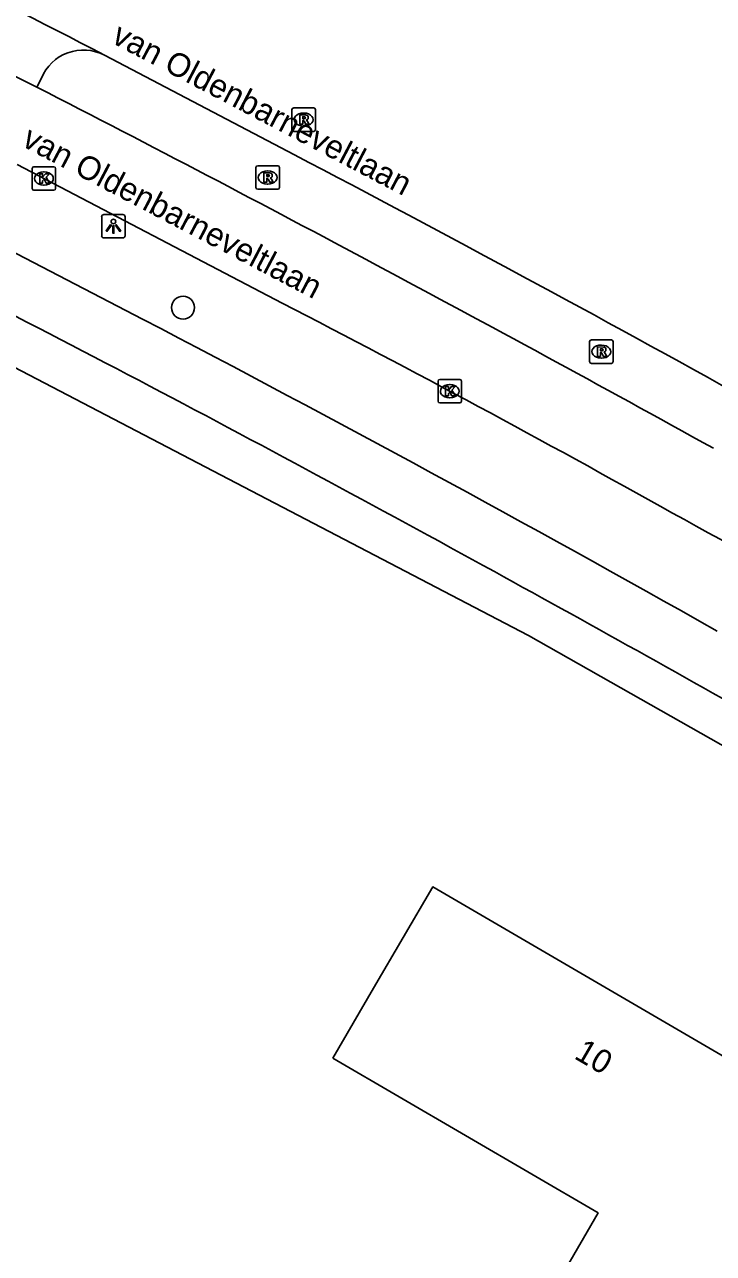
# Model space of a CAD drawing. Extents: x 162417 to 163721, y 384268 to 385416.
# Drawn here: x 163258.8 to 163288.2, y 385291.7 to 385344.1 of the extents above; entities that cross this region are included whole.
import ezdxf

# ---------------------------------------------------------------- set-up
doc = ezdxf.new("R2010")
doc.units = 0
for name, color, linetype in [('IMGEO_Boom', 7, 'Continuous'), ('IMGEO_Fietspad_open', 7, 'Continuous'), ('IMGEO_Kolk', 7, 'Continuous'), ('IMGEO_Lichtpunt', 7, 'Continuous'), ('IMGEO_Openbare_ruimte_label', 7, 'Continuous'), ('IMGEO_Pand', 7, 'Continuous'), ('IMGEO_Pand_nummerreeks', 7, 'Continuous'), ('IMGEO_Rijbaan_lokaal_gesloten', 7, 'Continuous'), ('IMGEO_Rijbaan_lokaal_open', 7, 'Continuous'), ('IMGEO_Rioolput', 7, 'Continuous'), ('IMGEO_Voetpad_open', 7, 'Continuous')]:
    doc.layers.add(name, color=color, linetype=linetype)

msp = doc.modelspace()

# ---------------------------------------------------------------- linework, layer by layer
at = {"layer": 'IMGEO_Boom'}
msp.add_circle((163265.554, 385332.056), 0.489, dxfattribs=at)
at = {"layer": 'IMGEO_Fietspad_open'}
msp.add_lwpolyline([(163254.163, 385336.585), (163263.832, 385331.566)], dxfattribs=at)
for centre, radius, start, end in [((162861.635, 384564.02), 864.147, 61.133149, 63.416417), ((162868.056, 384573.863), 854.84, 60.5517, 62.420278), ((162780.171, 384413.91), 1034.935, 59.552708, 61.195582)]:
    msp.add_arc(centre, radius, start, end, dxfattribs=at)
at = {"layer": 'IMGEO_Kolk'}
for p, q in [((163259.122, 385337.139), (163259.122, 385337.991)), ((163259.197, 385338.065), (163260.049, 385338.065)), ((163260.123, 385337.991), (163260.123, 385337.139)), ((163259.61, 385337.845), (163259.635, 385337.845)), ((163260.049, 385337.065), (163259.197, 385337.065)), ((163259.633, 385337.285), (163259.608, 385337.285)), ((163276.423, 385328.064), (163276.423, 385328.916)), ((163276.498, 385328.99), (163277.35, 385328.99)), ((163276.911, 385328.77), (163276.936, 385328.77)), ((163277.424, 385328.916), (163277.424, 385328.064)), ((163277.35, 385327.99), (163276.498, 385327.99)), ((163276.934, 385328.21), (163276.909, 385328.21))]:
    msp.add_line(p, q, dxfattribs=at)
for points in [[(163259.122, 385337.139), (163259.122, 385337.991)], [(163259.197, 385338.065), (163260.049, 385338.065)], [(163260.123, 385337.991), (163260.123, 385337.139)], [(163259.443, 385337.765), (163259.566, 385337.765), (163259.566, 385337.614), (163259.696, 385337.765), (163259.86, 385337.765), (163259.714, 385337.614), (163259.867, 385337.365), (163259.715, 385337.365), (163259.63, 385337.529), (163259.566, 385337.462), (163259.566, 385337.365), (163259.443, 385337.365), (163259.443, 385337.765)], [(163260.049, 385337.065), (163259.197, 385337.065)], [(163276.423, 385328.064), (163276.423, 385328.916)], [(163276.498, 385328.99), (163277.35, 385328.99)], [(163276.744, 385328.69), (163276.867, 385328.69), (163276.867, 385328.539), (163276.997, 385328.69), (163277.161, 385328.69), (163277.015, 385328.539), (163277.168, 385328.29), (163277.016, 385328.29), (163276.931, 385328.454), (163276.867, 385328.387), (163276.867, 385328.29), (163276.744, 385328.29), (163276.744, 385328.69)], [(163277.424, 385328.916), (163277.424, 385328.064)], [(163277.35, 385327.99), (163276.498, 385327.99)]]:
    msp.add_lwpolyline(points, dxfattribs=at)
for centre, start, end in [((163259.199, 385337.989), 91.552, 178.448), ((163259.199, 385337.989), 91.552, 178.448), ((163260.047, 385337.989), 1.552, 88.448), ((163260.047, 385337.989), 1.552, 88.448), ((163259.199, 385337.141), 181.552, 268.448), ((163259.199, 385337.141), 181.552, 268.448), ((163260.047, 385337.141), 271.552, 358.448), ((163260.047, 385337.141), 271.552, 358.448), ((163276.5, 385328.914), 91.552, 178.448), ((163276.5, 385328.914), 91.552, 178.448), ((163277.348, 385328.914), 1.552, 88.448), ((163277.348, 385328.914), 1.552, 88.448), ((163276.5, 385328.066), 181.552, 268.448), ((163276.5, 385328.066), 181.552, 268.448), ((163277.348, 385328.066), 271.552, 358.448), ((163277.348, 385328.066), 271.552, 358.448)]:
    msp.add_arc(centre, 0.0765, start, end, dxfattribs=at)
for centre, major_axis, ratio, start_param, end_param in [((163259.609, 385337.565), (-0.387, 0.002), 0.722429, 4.712389, 7.853982), ((163259.634, 385337.565), (-0.39, 0.002), 0.717154, 1.570796, 4.712389), ((163276.91, 385328.49), (-0.387, 0.002), 0.722429, 4.712389, 7.853982), ((163276.935, 385328.49), (-0.39, 0.002), 0.717154, 1.570796, 4.712389)]:
    msp.add_ellipse(centre, major_axis=major_axis, ratio=ratio, start_param=start_param, end_param=end_param, dxfattribs=at)
at = {"layer": 'IMGEO_Lichtpunt'}
for p, q in [((163262.085, 385335.931), (163262.085, 385335.124)), ((163262.085, 385335.931), (163262.085, 385335.124)), ((163262.987, 385336.026), (163262.179, 385336.026)), ((163262.987, 385336.026), (163262.179, 385336.026)), ((163263.081, 385335.124), (163263.081, 385335.931)), ((163263.081, 385335.124), (163263.081, 385335.931)), ((163262.179, 385335.03), (163262.987, 385335.03)), ((163262.179, 385335.03), (163262.987, 385335.03))]:
    msp.add_line(p, q, dxfattribs=at)
for points in [[(163262.459, 385335.595), (163262.498, 385335.567), (163262.31, 385335.305), (163262.272, 385335.332), (163262.459, 385335.595)], [(163262.561, 385335.547), (163262.608, 385335.547), (163262.608, 385335.225), (163262.561, 385335.225), (163262.561, 385335.547)], [(163262.671, 385335.567), (163262.709, 385335.594), (163262.896, 385335.332), (163262.857, 385335.304), (163262.671, 385335.567)]]:
    msp.add_lwpolyline(points, dxfattribs=at)
msp.add_circle((163262.584, 385335.729), 0.0994, dxfattribs=at)
for centre, start, end in [((163262.179, 385335.931), 90, 180), ((163262.179, 385335.931), 90, 180), ((163262.987, 385335.931), 0, 90), ((163262.987, 385335.931), 0, 90), ((163262.179, 385335.124), 180, 270), ((163262.179, 385335.124), 180, 270), ((163262.987, 385335.124), 270, 0), ((163262.987, 385335.124), 270, 360)]:
    msp.add_arc(centre, 0.0946, start, end, dxfattribs=at)
at = {"layer": 'IMGEO_Pand'}
msp.add_lwpolyline([(163271.934, 385300.031), (163273.678, 385303.02), (163276.197, 385307.338), (163292.739, 385297.685), (163292.512, 385297.296), (163288.42, 385290.282), (163292.911, 385287.661), (163284.217, 385272.761), (163279.899, 385275.28), (163276.875, 385277.044), (163277, 385277.259), (163277.431, 385277.007), (163284.546, 385289.202), (163281.738, 385290.839), (163283.249, 385293.43), (163271.934, 385300.031)], dxfattribs=at)
at = {"layer": 'IMGEO_Rijbaan_lokaal_gesloten'}
for points in [[(163259.326, 385341.462), (163256.813, 385342.718), (163246.464, 385347.868)], [(163262.2, 385342.827), (163270.31, 385338.574)], [(163258.488, 385338.155), (163269.784, 385332.244)]]:
    msp.add_lwpolyline(points, dxfattribs=at)
for centre, radius, start, end in [((163041.904, 384919.915), 476.849, 62.48489, 64.68209), ((162780.756, 384411.16), 1046.18, 60.986906, 62.777614), ((162832.495, 384505.225), 941.357, 60.941053, 62.284021), ((163022.094, 384852.214), 540.166, 60.70323, 62.70676), ((163050.012, 384890.752), 492.926, 59.1843, 61.34126)]:
    msp.add_arc(centre, radius, start, end, dxfattribs=at)
at = {"layer": 'IMGEO_Rijbaan_lokaal_open'}
msp.add_lwpolyline([(163259.513, 385341.847), (163259.326, 385341.462)], dxfattribs=at)
msp.add_arc((163261.307, 385341.103), 1.942, 62.6131, 157.4626, dxfattribs=at)
at = {"layer": 'IMGEO_Rioolput'}
for p, q in [((163270.273, 385340.576), (163271.125, 385340.576)), ((163270.198, 385339.65), (163270.198, 385340.502)), ((163270.686, 385340.356), (163270.711, 385340.356)), ((163271.199, 385340.502), (163271.199, 385339.65)), ((163271.125, 385339.576), (163270.273, 385339.576)), ((163270.709, 385339.796), (163270.684, 385339.796)), ((163268.661, 385337.18), (163268.661, 385338.032)), ((163268.736, 385338.106), (163269.588, 385338.106)), ((163269.662, 385338.032), (163269.662, 385337.18)), ((163269.149, 385337.886), (163269.174, 385337.886)), ((163269.588, 385337.106), (163268.736, 385337.106)), ((163269.172, 385337.326), (163269.147, 385337.326)), ((163282.886, 385329.751), (163282.886, 385330.603)), ((163282.961, 385330.677), (163283.813, 385330.677)), ((163283.887, 385330.603), (163283.887, 385329.751)), ((163283.374, 385330.457), (163283.399, 385330.457)), ((163283.813, 385329.677), (163282.961, 385329.677)), ((163283.397, 385329.897), (163283.372, 385329.897))]:
    msp.add_line(p, q, dxfattribs=at)
for points in [[(163270.273, 385340.576), (163271.125, 385340.576)], [(163270.198, 385339.65), (163270.198, 385340.502)], [(163270.787, 385340.274), (163270.535, 385340.276), (163270.535, 385339.876)], [(163270.535, 385339.876), (163270.659, 385339.876), (163270.659, 385340.038), (163270.67, 385340.038)], [(163270.713, 385340.195), (163270.659, 385340.195), (163270.659, 385340.114)], [(163270.659, 385340.114), (163270.711, 385340.114)], [(163271.199, 385340.502), (163271.199, 385339.65)], [(163271.125, 385339.576), (163270.273, 385339.576)], [(163270.717, 385340.009), (163270.788, 385339.876), (163270.928, 385339.876), (163270.863, 385340.002)], [(163268.661, 385337.18), (163268.661, 385338.032)], [(163268.736, 385338.106), (163269.588, 385338.106)], [(163269.662, 385338.032), (163269.662, 385337.18)], [(163269.25, 385337.804), (163268.998, 385337.806), (163268.998, 385337.406)], [(163268.998, 385337.406), (163269.122, 385337.406), (163269.122, 385337.568), (163269.133, 385337.568)], [(163269.176, 385337.725), (163269.122, 385337.725), (163269.122, 385337.644)], [(163269.122, 385337.644), (163269.174, 385337.644)], [(163269.18, 385337.539), (163269.251, 385337.406), (163269.391, 385337.406), (163269.326, 385337.532)], [(163269.588, 385337.106), (163268.736, 385337.106)], [(163282.886, 385329.751), (163282.886, 385330.603)], [(163282.961, 385330.677), (163283.813, 385330.677)], [(163283.887, 385330.603), (163283.887, 385329.751)], [(163283.475, 385330.375), (163283.223, 385330.377), (163283.223, 385329.977)], [(163283.223, 385329.977), (163283.347, 385329.977), (163283.347, 385330.139), (163283.358, 385330.139)], [(163283.401, 385330.296), (163283.347, 385330.296), (163283.347, 385330.215)], [(163283.347, 385330.215), (163283.399, 385330.215)], [(163283.405, 385330.11), (163283.476, 385329.977), (163283.616, 385329.977), (163283.551, 385330.103)], [(163283.813, 385329.677), (163282.961, 385329.677)]]:
    msp.add_lwpolyline(points, dxfattribs=at)
for centre, radius, start, end in [((163270.275, 385340.5), 0.0765, 91.552, 178.448), ((163270.275, 385340.5), 0.0765, 91.552, 178.448), ((163271.123, 385340.5), 0.0765, 1.552, 88.448), ((163271.123, 385340.5), 0.0765, 1.552, 88.448), ((163270.669, 385339.985), 0.0533, 26.0293, 88.6989), ((163270.695, 385340.303), 0.19, 274.7715, 282.9687), ((163270.719, 385340.099), 0.0964, 77.0061, 93.1865), ((163270.733, 385340.156), 0.0378, 276.6634, 79.6772), ((163270.786, 385340.164), 0.109, 350.3612, 89.416), ((163270.784, 385340.164), 0.112, 277.5842, 350.9817), ((163270.768, 385339.949), 0.108, 29.5134, 73.7905), ((163270.275, 385339.652), 0.0765, 181.552, 268.448), ((163270.275, 385339.652), 0.0765, 181.552, 268.448), ((163271.123, 385339.652), 0.0765, 271.552, 358.448), ((163271.123, 385339.652), 0.0765, 271.552, 358.448), ((163268.738, 385338.03), 0.0765, 91.552, 178.448), ((163268.738, 385338.03), 0.0765, 91.552, 178.448), ((163269.586, 385338.03), 0.0765, 1.552, 88.448), ((163269.586, 385338.03), 0.0765, 1.552, 88.448), ((163269.132, 385337.515), 0.0533, 26.0293, 88.6989), ((163269.158, 385337.833), 0.19, 274.7715, 282.9687), ((163269.182, 385337.629), 0.0964, 77.0061, 93.1865), ((163269.196, 385337.686), 0.0378, 276.6634, 79.6772), ((163269.249, 385337.694), 0.109, 350.3612, 89.416), ((163269.247, 385337.694), 0.112, 277.5842, 350.9817), ((163269.231, 385337.479), 0.108, 29.5134, 73.7905), ((163268.738, 385337.182), 0.0765, 181.552, 268.448), ((163268.738, 385337.182), 0.0765, 181.552, 268.448), ((163269.586, 385337.182), 0.0765, 271.552, 358.448), ((163269.586, 385337.182), 0.0765, 271.552, 358.448), ((163282.963, 385330.601), 0.0765, 91.552, 178.448), ((163282.963, 385330.601), 0.0765, 91.552, 178.448), ((163283.811, 385330.601), 0.0765, 1.552, 88.448), ((163283.811, 385330.601), 0.0765, 1.552, 88.448), ((163283.357, 385330.086), 0.0533, 26.0293, 88.6989), ((163283.383, 385330.404), 0.19, 274.7715, 282.9687), ((163283.407, 385330.2), 0.0964, 77.0061, 93.1865), ((163283.421, 385330.257), 0.0378, 276.6634, 79.6772), ((163283.474, 385330.265), 0.109, 350.3612, 89.416), ((163283.472, 385330.265), 0.112, 277.5842, 350.9817), ((163283.456, 385330.05), 0.108, 29.5134, 73.7905), ((163282.963, 385329.753), 0.0765, 181.552, 268.448), ((163282.963, 385329.753), 0.0765, 181.552, 268.448), ((163283.811, 385329.753), 0.0765, 271.552, 358.448), ((163283.811, 385329.753), 0.0765, 271.552, 358.448)]:
    msp.add_arc(centre, radius, start, end, dxfattribs=at)
for centre, major_axis, ratio, start_param, end_param in [((163270.685, 385340.076), (-0.387, 0.002), 0.722429, 4.712389, 7.853982), ((163270.71, 385340.076), (-0.39, 0.002), 0.717154, 1.570796, 4.712389), ((163269.148, 385337.606), (-0.387, 0.002), 0.722429, 4.712389, 7.853982), ((163269.173, 385337.606), (-0.39, 0.002), 0.717154, 1.570796, 4.712389), ((163283.373, 385330.177), (-0.387, 0.002), 0.722429, 4.712389, 7.853982), ((163283.398, 385330.177), (-0.39, 0.002), 0.717154, 1.570796, 4.712389)]:
    msp.add_ellipse(centre, major_axis=major_axis, ratio=ratio, start_param=start_param, end_param=end_param, dxfattribs=at)
at = {"layer": 'IMGEO_Voetpad_open'}
msp.add_lwpolyline([(163307.686, 385302.216), (163291.557, 385311.67), (163280.277, 385318.062), (163247.492, 385335.181), (163246.263, 385335.823), (163212.847, 385351.737), (163184.213, 385364.005), (163174.141, 385368.012), (163167.217, 385370.454)], dxfattribs=at)

# ---------------------------------------------------------------- texts
at = {"layer": 'IMGEO_Openbare_ruimte_label'}
for p in [(163262.452, 385343.38), (163258.627, 385338.978)]:
    msp.add_text('van Oldenbarneveltlaan', height=1, rotation=332.2815, dxfattribs=at).set_placement(p)
at = {"layer": 'IMGEO_Pand_nummerreeks'}
msp.add_text('10', height=1, rotation=329.7345, dxfattribs=at).set_placement((163282.182, 385300.048))

doc.saveas('drawing.dxf')
